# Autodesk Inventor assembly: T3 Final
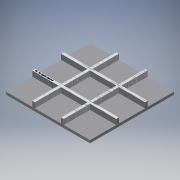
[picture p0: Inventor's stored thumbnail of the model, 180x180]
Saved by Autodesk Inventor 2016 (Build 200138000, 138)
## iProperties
Created: 2017-05
Part Number: T3 Final
Document SubType Name: Assembly
Designer: 8643301
RuleStatus: InUse
AfterDocOpen0: Welcome
Author: 8643301
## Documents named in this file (5)
- D:\IED Agnim Agarwal\IED - Agnim Agarwal\Final Project\Tic-Tac-Toe\T3 Final.iam
- D:\IED Agnim Agarwal\IED - Agnim Agarwal\Final Project\Tic-Tac-Toe\Board.ipt
- D:\IED Agnim Agarwal\IED - Agnim Agarwal\Final Project\Tic-Tac-Toe\X.ipt
- D:\IED Agnim Agarwal\IED - Agnim Agarwal\Final Project\Tic-Tac-Toe\O.ipt
- D:\IED Agnim Agarwal\IED - Agnim Agarwal\Final Project\Tic-Tac-Toe\Square.ipt
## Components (28 placed, 12 different names)
1. 0 — Mate:1, Mate:2, Mate:3, Mate:4, Mate:5, Mate:6, Mate:7, Mate:8, Mate:9, Mate:10, Mate:11, Mate:12, Mate:13, Mate:14, Mate:15, Mate:16, Mate:17, Mate:18, Mate:19, Mate:20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
2. X:1 — Mate:1, Mate:10, Mate:11
3. X:2 — Mate:2, Mate:12, Mate:13
4. X:3 — Mate:3, Mate:14, Mate:15
5. X:4 — Mate:4, Mate:16, Mate:17
6. X:5 — Mate:5, Mate:18, Mate:19
7. X:6 — Mate:6, Mate:20, Mate:21
8. X:7 — Mate:7, Mate:22, Mate:23
9. X:8 — Mate:8, Flush:1, Mate:24
10. X:9 — Mate:9, Flush:2, Mate:25
11. O:1 — Mate:26, Mate:35, Mate:36
12. O:2 — Mate:27, Mate:37, Flush:3
13. O:3 — Mate:28, Mate:38, Flush:4
14. O:4 — Mate:29, Mate:39, Mate:40
15. O:5 — Mate:30, Mate:41, Mate:42
16. O:6 — Mate:31, Mate:43, Flush:5
17. O:7 — Mate:32, Mate:44, Flush:6
18. O:8 — Mate:33, Flush:7, Mate:45
19. O:9 — Mate:34, Mate:46, Mate:47
20. 1 — Mate:51, Mate:52, Mate:53
21. 2 — Mate:54, Flush:8, Mate:55
22. 3 — Mate:56, Flush:9, Mate:57
23. 4 — Mate:58, Flush:10, Mate:59
24. 5 — Mate:60, Mate:61, Mate:62
25. 6 — Mate:63, Mate:64, Flush:11
26. 7 — Mate:48, Mate:49, Mate:50
27. 8 — Mate:65, Mate:66, Flush:12
28. 9 — Mate:67, Flush:13, Flush:14
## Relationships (81: Mate 67, Flush 14)
- Mate:1: 0 ↔ X:1
- Mate:2: 0 ↔ X:2
- Mate:3: 0 ↔ X:3
- Mate:4: 0 ↔ X:4
- Mate:5: 0 ↔ X:5
- Mate:6: 0 ↔ X:6
- Mate:7: 0 ↔ X:7
- Mate:8: 0 ↔ X:8
- Mate:9: 0 ↔ X:9
- Mate:10: 0 ↔ X:1
- Mate:11: 0 ↔ X:1
- Mate:12: 0 ↔ X:2
- Mate:13: 0 ↔ X:2
- Mate:14: 0 ↔ X:3
- Mate:15: 0 ↔ X:3
- Mate:16: 0 ↔ X:4
- Mate:17: 0 ↔ X:4
- Mate:18: 0 ↔ X:5
- Mate:19: 0 ↔ X:5
- Mate:20: 0 ↔ X:6
- Mate:21: 0 ↔ X:6
- Mate:22: 0 ↔ X:7
- Mate:23: 0 ↔ X:7
- Flush:1: 0 ↔ X:8
- Mate:24: 0 ↔ X:8
- Flush:2: 0 ↔ X:9
- Mate:25: 0 ↔ X:9
- Mate:26: 0 ↔ O:1
- Mate:27: 0 ↔ O:2
- Mate:28: 0 ↔ O:3
- Mate:29: 0 ↔ O:4
- Mate:30: 0 ↔ O:5
- Mate:31: 0 ↔ O:6
- Mate:32: 0 ↔ O:7
- Mate:33: 0 ↔ O:8
- Mate:34: 0 ↔ O:9
- Mate:35: 0 ↔ O:1
- Mate:36: 0 ↔ O:1
- Mate:37: 0 ↔ O:2
- Flush:3: 0 ↔ O:2
- Mate:38: 0 ↔ O:3
- Flush:4: 0 ↔ O:3
- Mate:39: 0 ↔ O:4
- Mate:40: 0 ↔ O:4
- Mate:41: 0 ↔ O:5
- Mate:42: 0 ↔ O:5
- Mate:43: 0 ↔ O:6
- Flush:5: 0 ↔ O:6
- Mate:44: 0 ↔ O:7
- Flush:6: 0 ↔ O:7
- Flush:7: 0 ↔ O:8
- Mate:45: 0 ↔ O:8
- Mate:46: 0 ↔ O:9
- Mate:47: 0 ↔ O:9
- Mate:48: 0 ↔ 7
- Mate:49: 0 ↔ 7
- Mate:50: 0 ↔ 7
- Mate:51: 0 ↔ 1
- Mate:52: 0 ↔ 1
- Mate:53: 0 ↔ 1
- Mate:54: 0 ↔ 2
- Flush:8: 0 ↔ 2
- Mate:55: 0 ↔ 2
- Mate:56: 0 ↔ 3
- Flush:9: 0 ↔ 3
- Mate:57: 0 ↔ 3
- Mate:58: 0 ↔ 4
- Flush:10: 0 ↔ 4
- Mate:59: 0 ↔ 4
- Mate:60: 0 ↔ 5
- Mate:61: 0 ↔ 5
- Mate:62: 0 ↔ 5
- Mate:63: 0 ↔ 6
- Mate:64: 0 ↔ 6
- Flush:11: 0 ↔ 6
- Mate:65: 0 ↔ 8
- Mate:66: 0 ↔ 8
- Flush:12: 0 ↔ 8
- Mate:67: 0 ↔ 9
- Flush:13: 0 ↔ 9
- Flush:14: 0 ↔ 9
